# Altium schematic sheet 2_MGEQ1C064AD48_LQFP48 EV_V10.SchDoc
size 292 x 203 mm; PageSetup: Record=PageOptions|CenterHorizontal=True|CenterVertical=True|PrintScale=1.11|XCorrection=1.00|YCorrection=1.00|PrintKind=0|BorderSize=5000000|LeftOffset=0|BottomOffset=0|Orientation=2|PaperLength=1000|PaperWidth=1000|Scale=100|PaperSource=7|PrintQuality=-4|MediaType=1|DitherType=10|PaperKind=A4 (210 x 297 mm)|PrintScaleMode=1
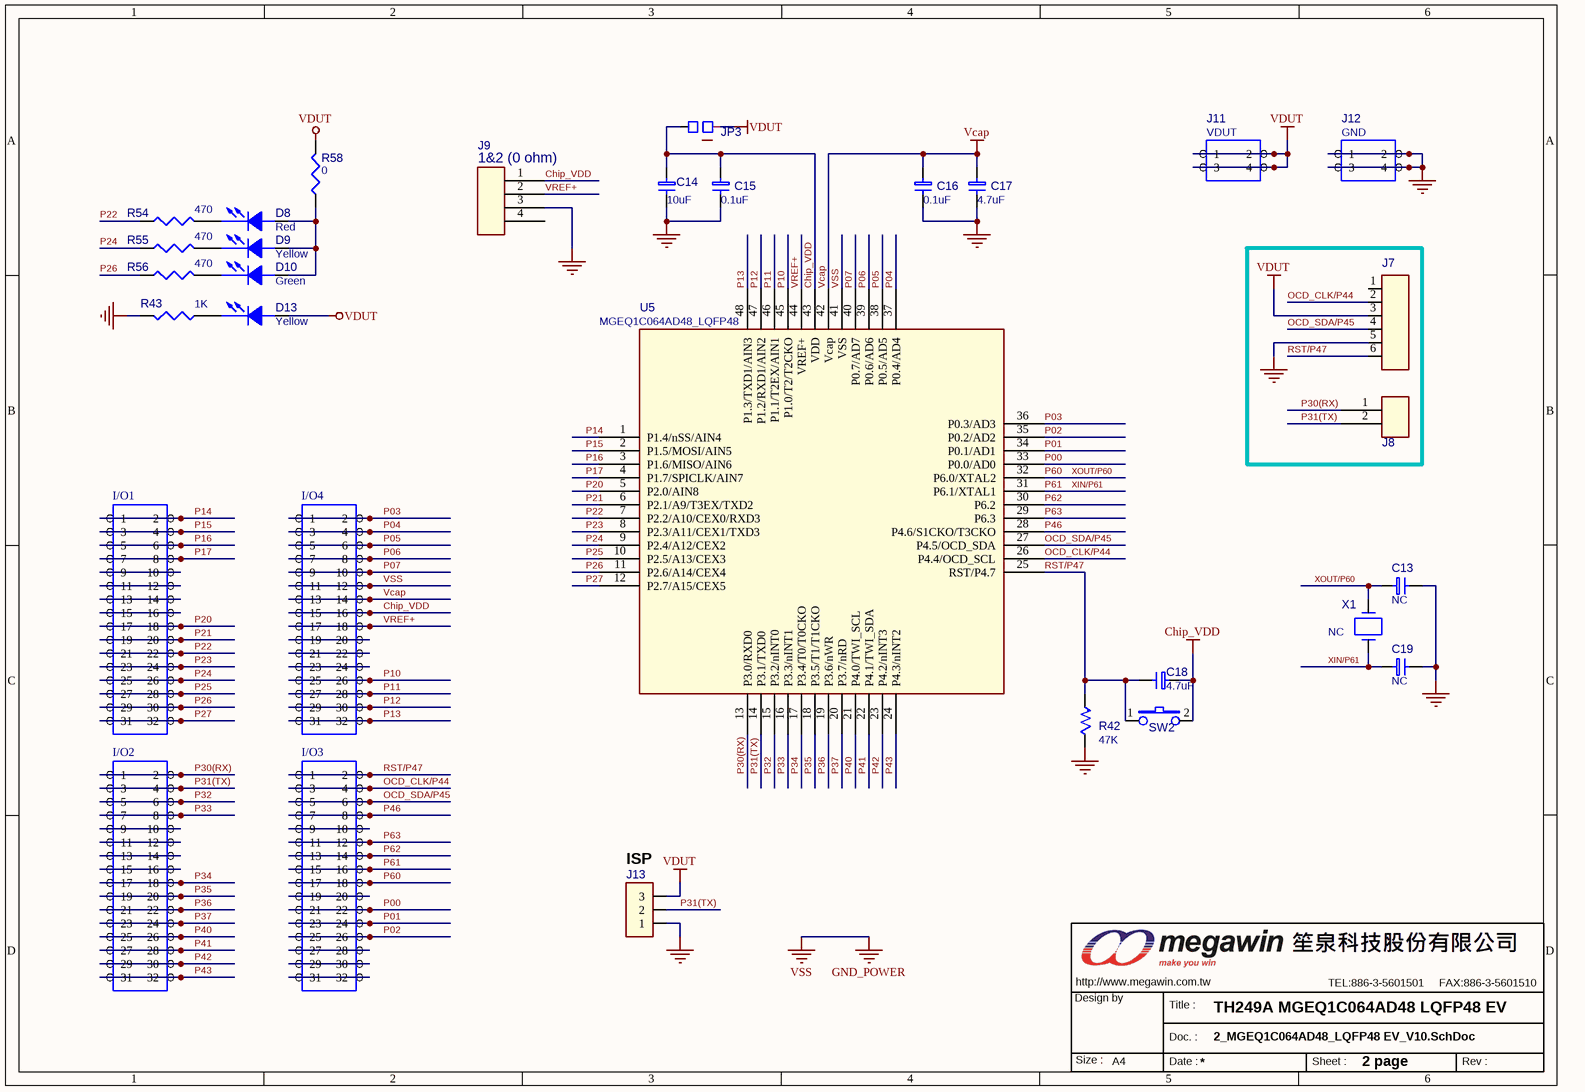
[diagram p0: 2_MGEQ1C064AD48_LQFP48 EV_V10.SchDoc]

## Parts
C13  NC  [0603C]
C14  10uF  [0603C]
C15  0.1uF  [0603C]
C16  0.1uF  [0603C]
C17  4.7uF  [0603C]
C18  4.7uF  [0603C]
C19  NC  [0603C]
D8  Red  [LED38+0805]
D9  Yellow  [LED38+0805]
D10  Green  [LED38+0805]
D13  Yellow  [0805D]
I/O1  CON16X2  [PS16X2P254]  (value not drawn)
I/O2  CON16X2  [PS16X2P254]  (value not drawn)
I/O3  CON16X2  [PS16X2P254]  (value not drawn)
I/O4  CON16X2  [PS16X2P254]  (value not drawn)
J7  CON6  [PS6P254]  (value not drawn)
J8  NC  [PS2P254]  (value not drawn)
J9  (no value)  [PS4P254]
J11  VDUT  [PS2X2P254]
J12  GND  [PS2X2P254]
J13  3P2.54_F_90  [PS3P254f_90]  (value not drawn)
JP3  JUMPER_2  [PS2P254]  (value not drawn)
MW1  OrgAddr3: TEL:886-3-5601501     FAX:886-3-5601510  [MEGAWIN_3.4]  (hidden comment: MW-A4)  (graphical)
R42  47K  [0603R]
R43  1K  [0603R]
R54  470  [0603R]
R55  470  [0603R]
R56  470  [0603R]
R58  0  [PS2p254+0603]
SW2  SW TACT-SPST  [SW_T_2P]  (value not drawn)
U5  MGEQ1C064AD48_LQFP48  [LQFP48_7X7_050]
X1  NC  [X49U]

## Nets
Chip_VDD: C14.1 C15.1 C18.1 I/O4.15 I/O4.16 J9.1 JP3.2 SW2.2 U5.43(VDD)
Vcap: C16.1 C17.1 I/O4.13 I/O4.14 U5.42(Vcap)
VDUT: D13.1(ANODE) J7.3 J11.1 J11.2 J11.3 J11.4 J13.3 JP3.1 R58.2
VSS: C13.2 C14.2 C15.2 C16.2 C17.2 C19.2 I/O4.11 I/O4.12 J7.5 J9.3 J12.1 J12.2 J12.3 J12.4 J13.1 R42.2 R43.1 U5.41(VSS)  [also labelled GND_POWER]
OCD_CLK/P44: I/O3.3 I/O3.4 J7.2 U5.26(P4.4/OCD_SCL)
OCD_SDA/P45: I/O3.5 I/O3.6 J7.4 U5.27(P4.5/OCD_SDA)
P00: I/O3.21 I/O3.22 U5.33(P0.0/AD0)
P01: I/O3.23 I/O3.24 U5.34(P0.1/AD1)
P02: I/O3.25 I/O3.26 U5.35(P0.2/AD2)
P03: I/O4.1 I/O4.2 U5.36(P0.3/AD3)
P04: I/O4.3 I/O4.4 U5.37(P0.4/AD4)
P05: I/O4.5 I/O4.6 U5.38(P0.5/AD5)
P06: I/O4.7 I/O4.8 U5.39(P0.6/AD6)
P07: I/O4.9 I/O4.10 U5.40(P0.7/AD7)
P10: I/O4.25 I/O4.26 U5.45(P1.0/T2/T2CKO)
P11: I/O4.27 I/O4.28 U5.46(P1.1/T2EX/AIN1)
P12: I/O4.29 I/O4.30 U5.47(P1.2/RXD1/AIN2)
P13: I/O4.31 I/O4.32 U5.48(P1.3/TXD1/AIN3)
P14: I/O1.1 I/O1.2 U5.1(P1.4/nSS/AIN4)
P15: I/O1.3 I/O1.4 U5.2(P1.5/MOSI/AIN5)
P16: I/O1.5 I/O1.6 U5.3(P1.6/MISO/AIN6)
P17: I/O1.7 I/O1.8 U5.4(P1.7/SPICLK/AIN7)
P20: I/O1.17 I/O1.18 U5.5(P2.0/AIN8)
P21: I/O1.19 I/O1.20 U5.6(P2.1/A9/T3EX/TXD2)
P22: I/O1.21 I/O1.22 R54.1 U5.7(P2.2/A10/CEX0/RXD3)
P23: I/O1.23 I/O1.24 U5.8(P2.3/A11/CEX1/TXD3)
P24: I/O1.25 I/O1.26 R55.1 U5.9(P2.4/A12/CEX2)
P25: I/O1.27 I/O1.28 U5.10(P2.5/A13/CEX3)
P26: I/O1.29 I/O1.30 R56.1 U5.11(P2.6/A14/CEX4)
P27: I/O1.31 I/O1.32 U5.12(P2.7/A15/CEX5)
P30(RX): I/O2.1 I/O2.2 J8.1 U5.13(P3.0/RXD0)
P31(TX): I/O2.3 I/O2.4 J8.2 J13.2 U5.14(P3.1/TXD0)
P32: I/O2.5 I/O2.6 U5.15(P3.2/nINT0)
P33: I/O2.7 I/O2.8 U5.16(P3.3/nINT1)
P34: I/O2.17 I/O2.18 U5.17(P3.4/T0/T0CKO)
P35: I/O2.19 I/O2.20 U5.18(P3.5/T1/T1CKO)
P36: I/O2.21 I/O2.22 U5.19(P3.6/nWR)
P37: I/O2.23 I/O2.24 U5.20(P3.7/nRD)
P40: I/O2.25 I/O2.26 U5.21(P4.0/TWI_SCL)
P41: I/O2.27 I/O2.28 U5.22(P4.1/TWI_SDA)
P42: I/O2.29 I/O2.30 U5.23(P4.2/nINT3)
P43: I/O2.31 I/O2.32 U5.24(P4.3/nINT2)
P46: I/O3.7 I/O3.8 U5.28(P4.6/S1CKO/T3CKO)
P60: C13.1 I/O3.17 I/O3.18 U5.32(P6.0/XTAL2) X1.1  [also labelled XOUT/P60]
P61: C19.1 I/O3.15 I/O3.16 U5.31(P6.1/XTAL1) X1.2  [also labelled XIN/P61]
P62: I/O3.13 I/O3.14 U5.30(P6.2)
P63: I/O3.11 I/O3.12 U5.29(P6.3)
RST/P47: C18.2 I/O3.1 I/O3.2 J7.6 R42.1 SW2.1 U5.25(RST/P4.7)
VREF+: I/O4.17 I/O4.18 J9.2 U5.44(VREF+)
NetD8_1: D8.1(ANODE) D9.1(ANODE) D10.1(ANODE) R58.1
NetD8_2: D8.2(CATHODE) R54.2
NetD9_2: D9.2(CATHODE) R55.2
NetD10_2: D10.2(CATHODE) R56.2
NetD13_2: D13.2(CATHODE) R43.2
NetI/O1_9: I/O1.9 I/O1.10
NetI/O1_11: I/O1.11 I/O1.12
NetI/O1_13: I/O1.13 I/O1.14
NetI/O1_15: I/O1.15 I/O1.16
NetI/O2_9: I/O2.9 I/O2.10
NetI/O2_11: I/O2.11 I/O2.12
NetI/O2_13: I/O2.13 I/O2.14
NetI/O2_15: I/O2.15 I/O2.16
NetI/O3_9: I/O3.9 I/O3.10
NetI/O3_19: I/O3.19 I/O3.20
NetI/O3_27: I/O3.27 I/O3.28
NetI/O3_29: I/O3.29 I/O3.30
NetI/O3_31: I/O3.31 I/O3.32
NetI/O4_19: I/O4.19 I/O4.20
NetI/O4_21: I/O4.21 I/O4.22
NetI/O4_23: I/O4.23 I/O4.24

Not connected (* = marked no-connect by the designer): J7 1; J9 4

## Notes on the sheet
- (near J9) 1&2 (0 ohm)
- (near J13) ISP
- TH249A MGEQ1C064AD48 LQFP48 EV
- 2 page

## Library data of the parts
C13-C19 = CAP: Capacitor
D8-D10 D13 = LED
J7 = CON6_Dup1
J8 = CON2
J9 = CON4
J11 J12 = CON2X2
J13 = CON3
JP3 = JUMPER_2: Jumper
MW1 = MW_A4_2
R42 = RES1
R43 R54-R56 R58 = R_Dup3
U5 = IC48_FA245_MGEQ1C064AD48
X1 = CRYSTAL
